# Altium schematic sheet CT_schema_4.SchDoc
size 322 x 309 mm
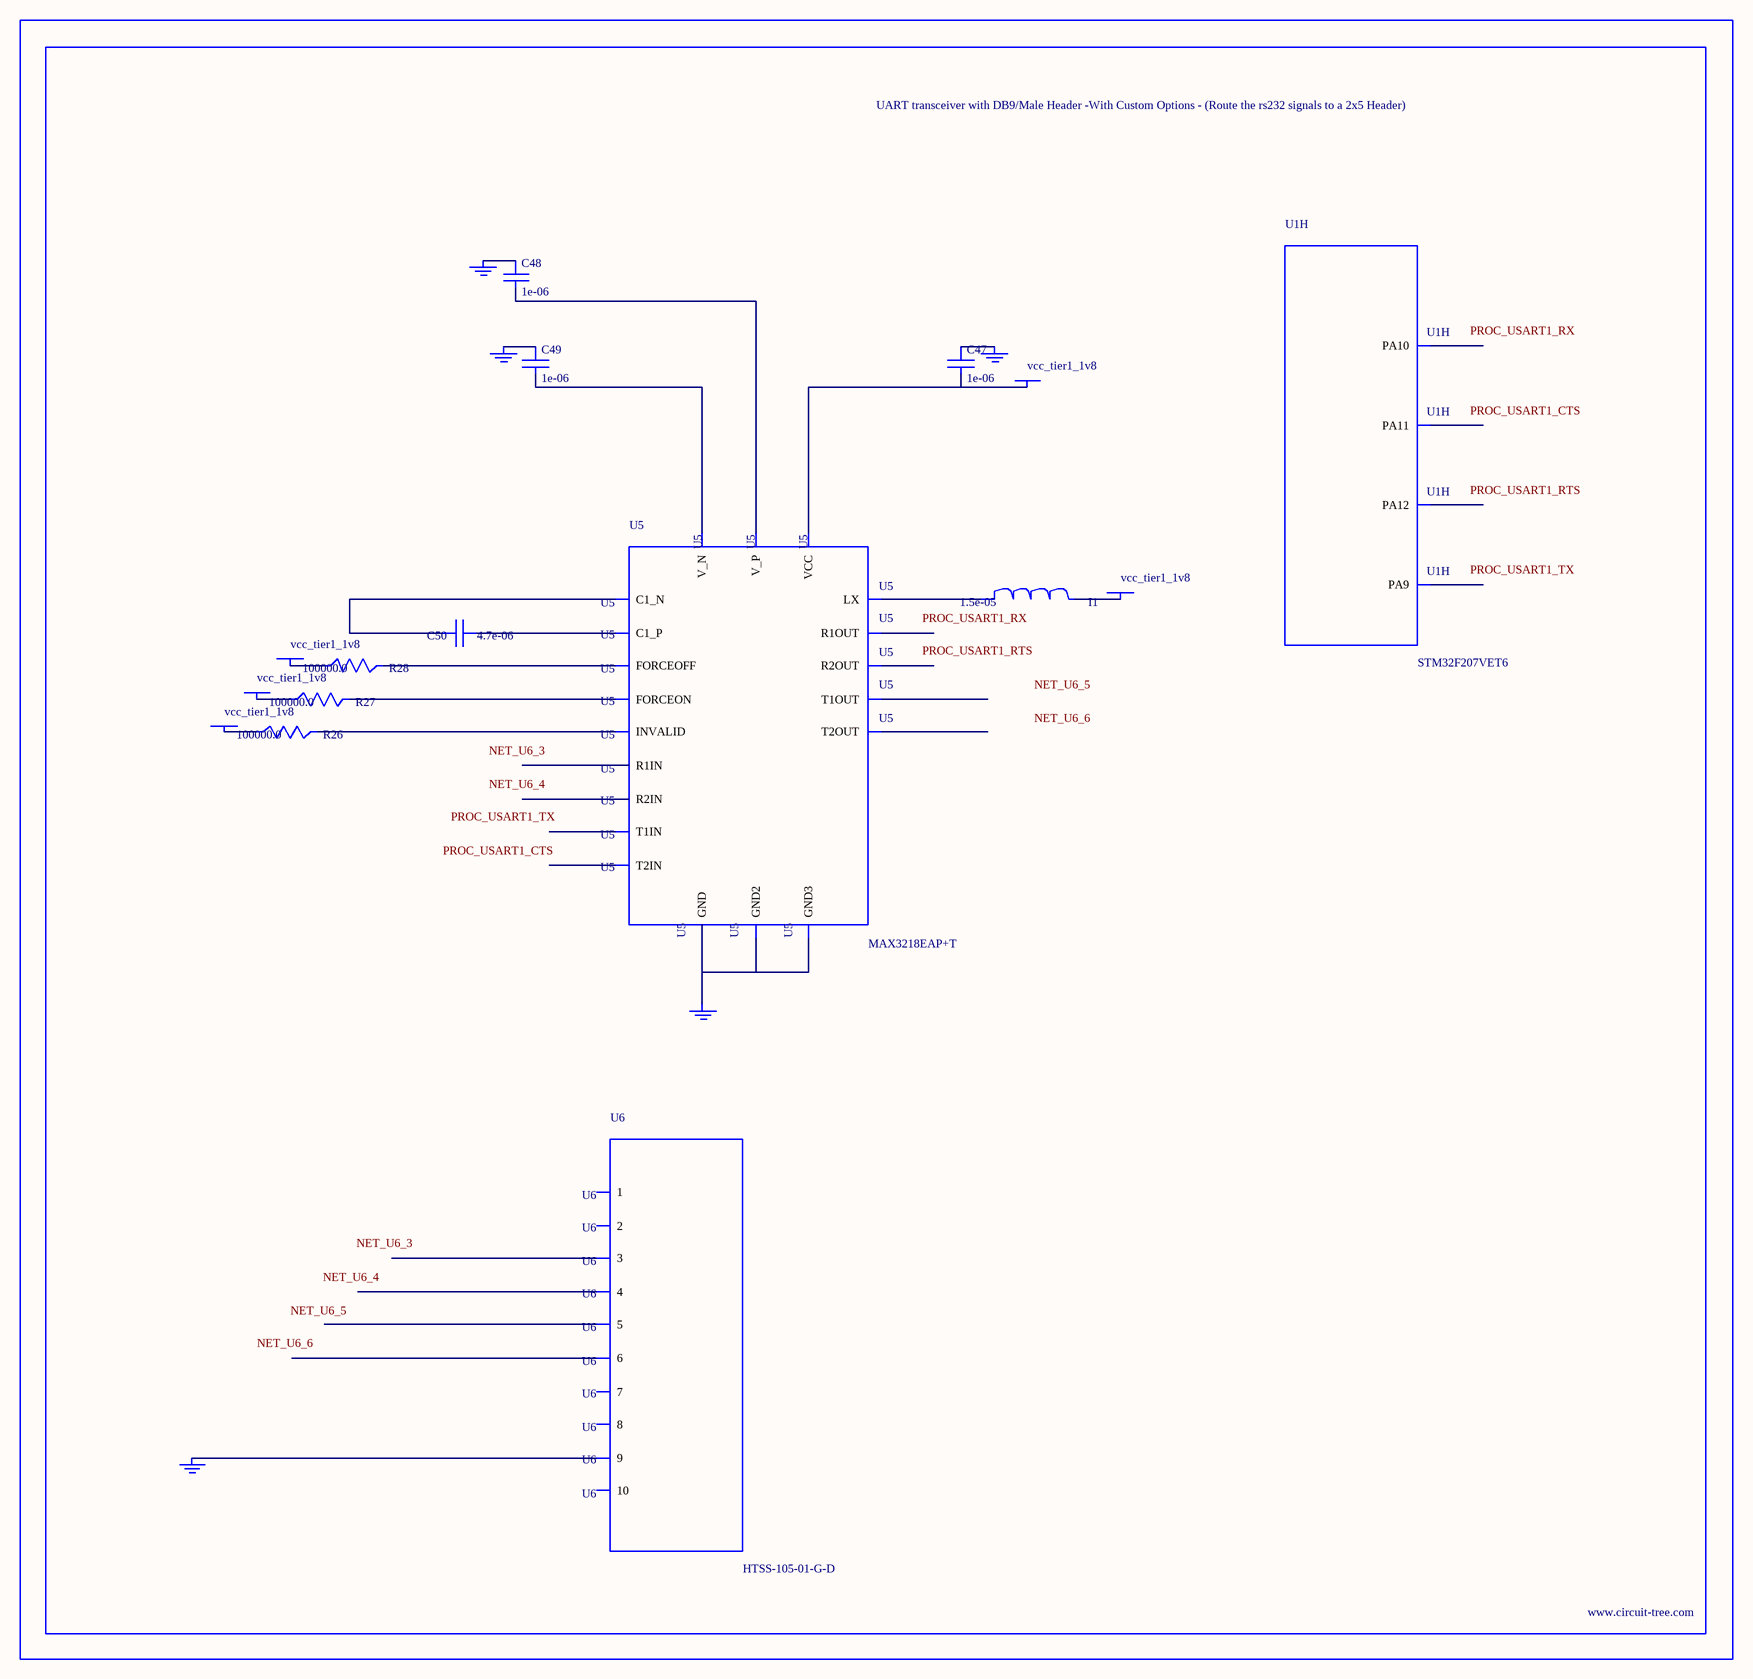
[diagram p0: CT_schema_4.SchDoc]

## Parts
BORDER3  (no value)
C47  1e-06  [C0603]
C48  1e-06  [C0603]
C49  1e-06  [C0603]
C50  4.7e-06  [C0805]
GND_INSTANCE_3_0  (no value)
GND_INSTANCE_3_1  (no value)
GND_INSTANCE_3_2  (no value)
GND_INSTANCE_3_3  (no value)
GND_INSTANCE_3_4  (no value)
I1  1.5e-05  [L1210]
POWER_INSTANCE_3_0  vcc_tier1_1v8
POWER_INSTANCE_3_1  vcc_tier1_1v8
POWER_INSTANCE_3_2  vcc_tier1_1v8
POWER_INSTANCE_3_3  vcc_tier1_1v8
POWER_INSTANCE_3_4  vcc_tier1_1v8
R26  100000.0  [R0603]
R27  100000.0  [R0603]
R28  100000.0  [R0603]
U1  STM32F207VET6  [LQFP100]  (part H of 9)
U5  MAX3218EAP+T  [SSOP-20]
U6  HTSS-105-01-G-D  [HTSS-105-01-G-D]

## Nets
NetC47_1: C47.1 GND_INSTANCE_3_0.0(GND)
NetC47_2: C47.2 POWER_INSTANCE_3_4.0(PWR) U5.6(VCC)
NetC48_1: C48.1 GND_INSTANCE_3_2.0(GND)
NetC48_2: C48.2 U5.19(V_P)
NetC49_1: C49.1 GND_INSTANCE_3_1.0(GND)
NetC49_2: C49.2 U5.15(V_N)
NetC50_1: C50.1 U5.18(C1_P)
NetC50_2: C50.2 U5.16(C1_N)
NetGND_INSTANCE_3_3_0: GND_INSTANCE_3_3.0(GND) U5.5(GND) U5.17(GND2) U5.20(GND3)
NetGND_INSTANCE_3_4_0: GND_INSTANCE_3_4.0(GND) U6.9
NetI1_1: I1.1 U5.1(LX)
NetI1_2: I1.2 POWER_INSTANCE_3_0.0(PWR)
NetPOWER_INSTANCE_3_1_0: POWER_INSTANCE_3_1.0(PWR) R26.1
NetPOWER_INSTANCE_3_2_0: POWER_INSTANCE_3_2.0(PWR) R27.1
NetPOWER_INSTANCE_3_3_0: POWER_INSTANCE_3_3.0(PWR) R28.1
NetR26_2: R26.2 U5.2(INVALID)
NetR27_2: R27.2 U5.3(FORCEON)
NetR28_2: R28.2 U5.4(FORCEOFF)

Not connected (* = marked no-connect by the designer): U1 68(PA9) 69(PA10) 70(PA11) 71(PA12); U5 7(T1IN) 8(T2IN) 9(R1OUT) 10(R2OUT) 11(R2IN) 12(R1IN) 13(T2OUT) 14(T1OUT); U6 1 2 3 4 5 6 7 8 10

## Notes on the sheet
- Labels drawn without touching a wire or pin: NET_U6_3, NET_U6_4, NET_U6_5, NET_U6_6, PROC_USART1_CTS, PROC_USART1_RTS, PROC_USART1_RX, PROC_USART1_TX

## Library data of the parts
BORDER3 = BORDER_PAGE3
C47-C49 = C0603C105K3RACTU
C50 = C0805C475K4RACTU
GND_INSTANCE_3_0-GND_INSTANCE_3_4 = GND
I1 = L1210R150MDWIT
POWER_INSTANCE_3_0-POWER_INSTANCE_3_4 = PWR
R26-R28 = RC0603JR-07100KL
